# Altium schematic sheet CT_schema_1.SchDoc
size 526 x 258 mm
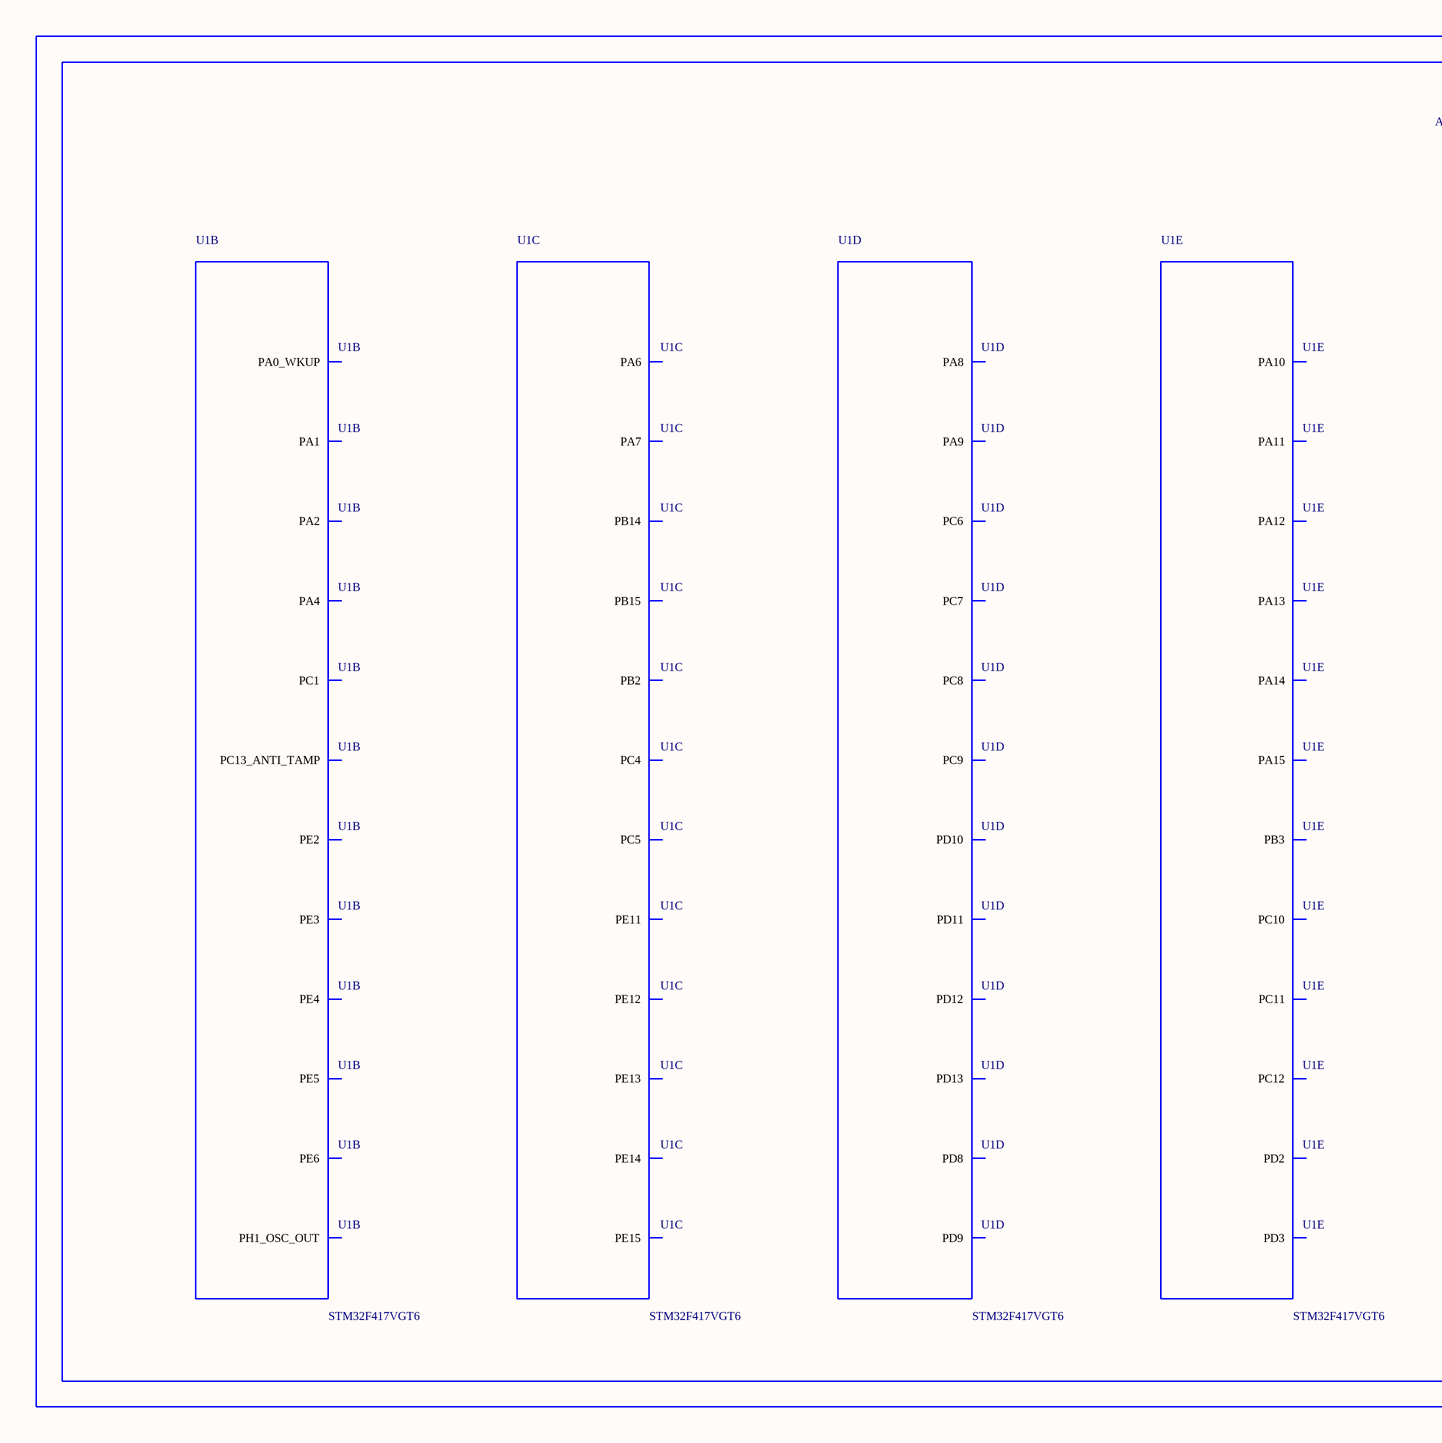
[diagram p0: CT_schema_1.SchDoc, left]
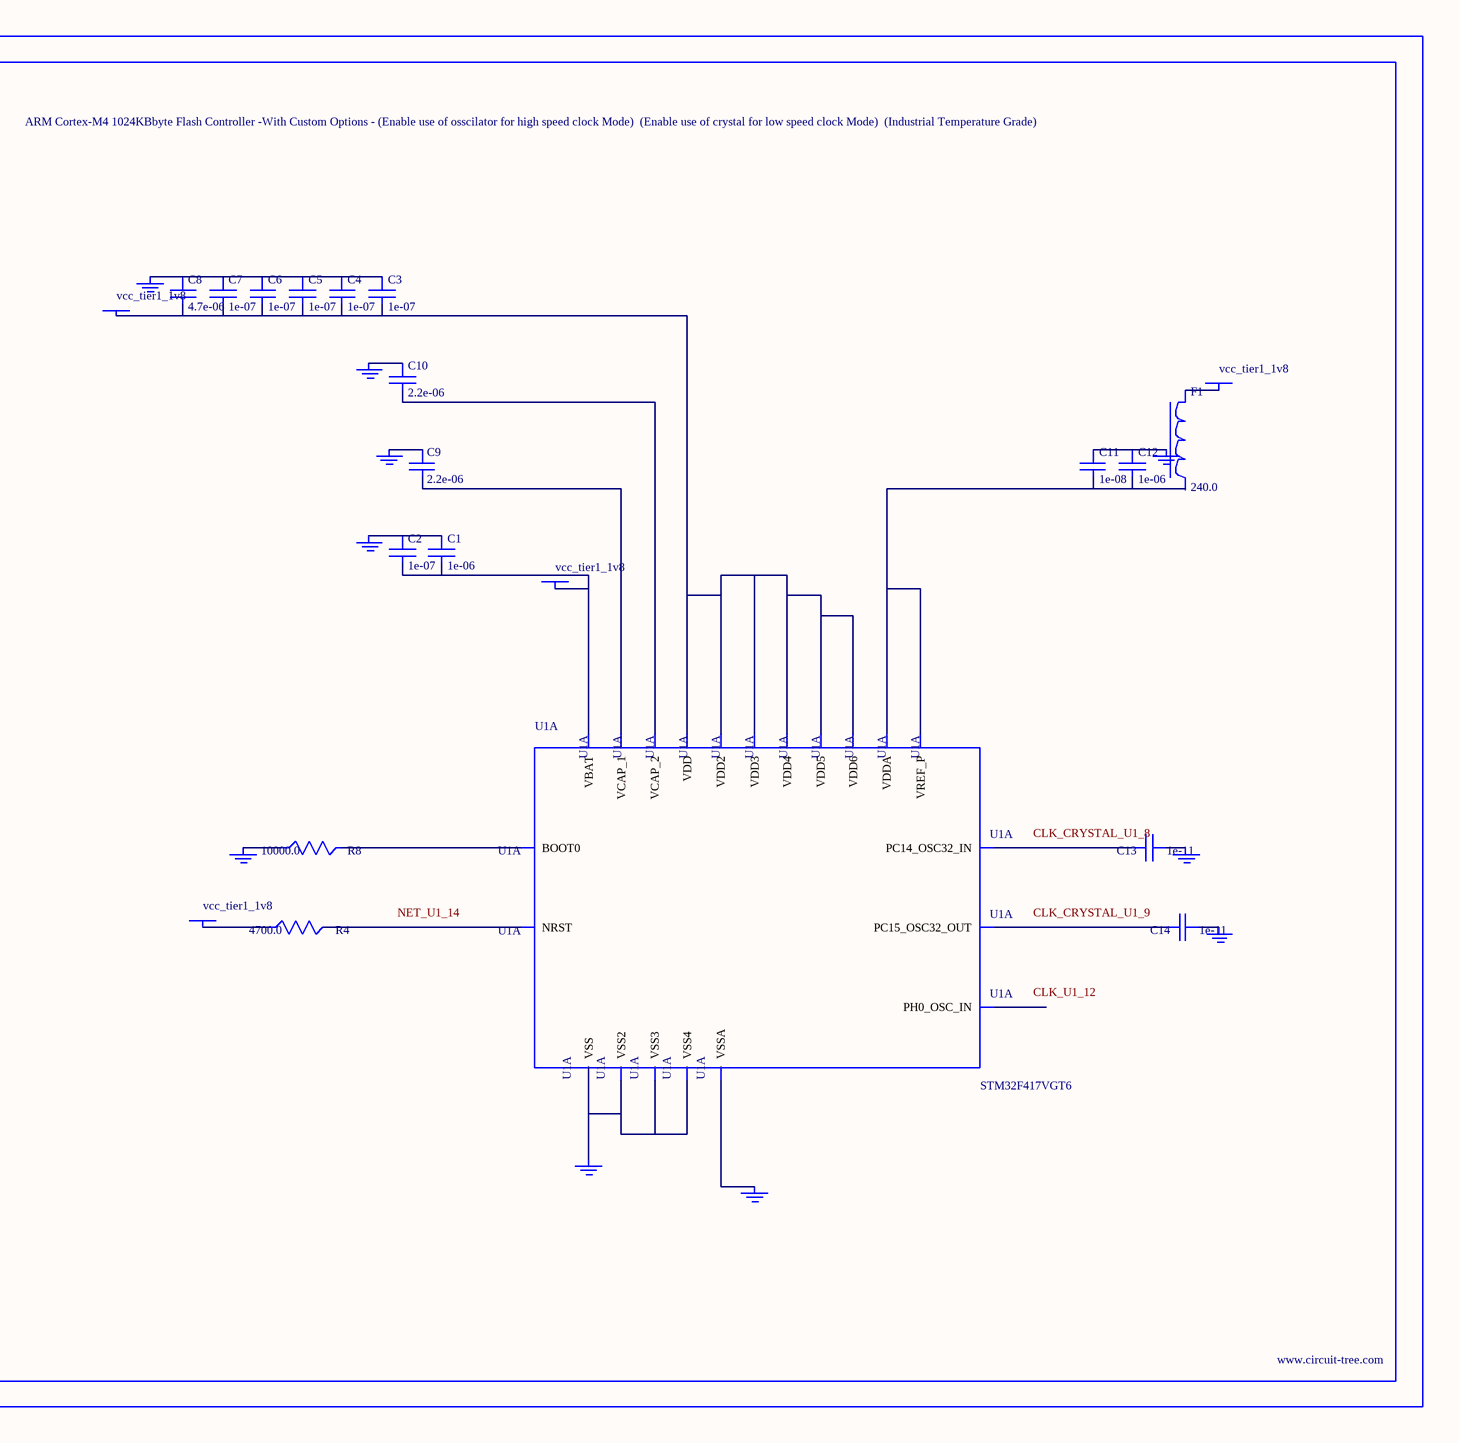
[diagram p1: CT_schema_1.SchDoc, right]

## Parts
BORDER0  (no value)
C1  1e-06  [C0603]
C2  1e-07  [C0603]
C3  1e-07  [C0603]
C4  1e-07  [C0603]
C5  1e-07  [C0603]
C6  1e-07  [C0603]
C7  1e-07  [C0603]
C8  4.7e-06  [C0603]
C9  2.2e-06  [C0603]
C10  2.2e-06  [C0603]
C11  1e-08  [C0603]
C12  1e-06  [C0603]
C13  1e-11  [C0402]
C14  1e-11  [C0402]
F1  240.0  [L0603]
GND_INSTANCE_0_0  (no value)
GND_INSTANCE_0_1  (no value)
GND_INSTANCE_0_2  (no value)
GND_INSTANCE_0_3  (no value)
GND_INSTANCE_0_4  (no value)
GND_INSTANCE_0_5  (no value)
GND_INSTANCE_0_6  (no value)
GND_INSTANCE_0_7  (no value)
GND_INSTANCE_0_8  (no value)
GND_INSTANCE_0_9  (no value)
POWER_INSTANCE_0_0  vcc_tier1_1v8
POWER_INSTANCE_0_1  vcc_tier1_1v8
POWER_INSTANCE_0_2  vcc_tier1_1v8
POWER_INSTANCE_0_3  vcc_tier1_1v8
R4  4700.0  [R0603]
R8  10000.0  [R0603]
U1  STM32F417VGT6  [LQFP100]  (parts A,B,C,D,E of 8)

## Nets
NetC1_1: C1.1 C2.1 GND_INSTANCE_0_0.0(GND)
NetC1_2: C1.2 C2.2 POWER_INSTANCE_0_0.0(PWR) U1.6(VBAT)
NetC3_1: C3.1 C4.1 C5.1 C6.1 C7.1 C8.1 GND_INSTANCE_0_3.0(GND)
NetC3_2: C3.2 C4.2 C5.2 C6.2 C7.2 C8.2 POWER_INSTANCE_0_1.0(PWR) U1.11(VDD) U1.19(VDD2) U1.28(VDD3) U1.50(VDD4) U1.75(VDD5) U1.100(VDD6)
NetC9_1: C9.1 GND_INSTANCE_0_6.0(GND)
NetC9_2: C9.2 U1.49(VCAP_1)
NetC10_1: C10.1 GND_INSTANCE_0_7.0(GND)
NetC10_2: C10.2 U1.73(VCAP_2)
NetC11_1: C11.1 C12.1 GND_INSTANCE_0_5.0(GND)
NetC11_2: C11.2 C12.2 U1.21(VREF_P) U1.22(VDDA)
NetC13_1: C13.1 GND_INSTANCE_0_1.0(GND)
NetC13_2: C13.2 U1.8(PC14_OSC32_IN)
NetC14_1: C14.1 GND_INSTANCE_0_2.0(GND)
NetC14_2: C14.2 U1.9(PC15_OSC32_OUT)
NetF1_1: F1.1 POWER_INSTANCE_0_2.0(PWR)
NetGND_INSTANCE_0_4_0: GND_INSTANCE_0_4.0(GND) U1.20(VSSA)
NetGND_INSTANCE_0_8_0: GND_INSTANCE_0_8.0(GND) R8.1
NetGND_INSTANCE_0_9_0: GND_INSTANCE_0_9.0(GND) U1.10(VSS) U1.27(VSS2) U1.74(VSS3) U1.99(VSS4)
NetPOWER_INSTANCE_0_3_0: POWER_INSTANCE_0_3.0(PWR) R4.1
NetR4_2: R4.2 U1.14(NRST)
NetR8_2: R8.2 U1.94(BOOT0)

Not connected (* = marked no-connect by the designer): F1 2; U1 1(PE2) 2(PE3) 3(PE4) 4(PE5) 5(PE6) 7(PC13_ANTI_TAMP) 12(PH0_OSC_IN) 13(PH1_OSC_OUT) 16(PC1) 23(PA0_WKUP) 24(PA1) 25(PA2) 29(PA4) 31(PA6) 32(PA7) 33(PC4) 34(PC5) 37(PB2) 42(PE11) 43(PE12) 44(PE13) 45(PE14) 46(PE15) 53(PB14) 54(PB15) 55(PD8) 56(PD9) 57(PD10) 58(PD11) 59(PD12) 60(PD13) 63(PC6) 64(PC7) 65(PC8) 66(PC9) 67(PA8) 68(PA9) 69(PA10) 70(PA11) 71(PA12) 72(PA13) 76(PA14) 77(PA15) 78(PC10) 79(PC11) 80(PC12) 83(PD2) 84(PD3) 89(PB3)

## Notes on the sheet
- Labels drawn without touching a wire or pin: CLK_CRYSTAL_U1_8, CLK_CRYSTAL_U1_9, CLK_U1_12, NET_U1_14

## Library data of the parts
BORDER0 = BORDER_PAGE0
C1 C12 = C0603C105K3RACTU
C2-C7 = 06035C104K4Z2A
C8 = GRM188R6YA475KE15D
C9 C10 = C0603C225K8RACTU
C11 = 06035C103K4Z2A
C13 C14 = C0402C100K3GACTU
F1 = Z0603C241ASMST
GND_INSTANCE_0_0-GND_INSTANCE_0_9 = GND
POWER_INSTANCE_0_0-POWER_INSTANCE_0_3 = PWR
R4 = RC0603JR-074K7L
R8 = RC0603JR-0710KL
